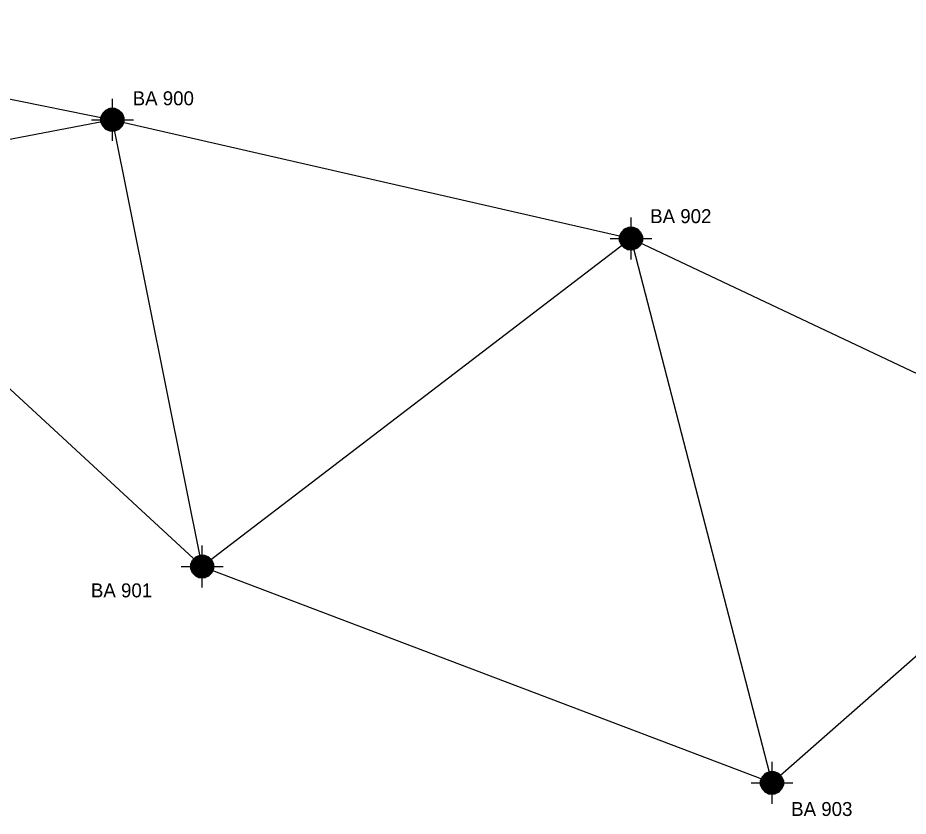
# Model space of a CAD drawing. Extents: x -346533 to -339969, y -1273090 to -1271585.
# Drawn here: x -345166.4 to -344688.1, y -1272911.2 to -1272482.5 of the extents above; entities that cross this region are included whole.
import ezdxf

# ---------------------------------------------------------------- set-up
doc = ezdxf.new("R2010")
doc.units = 0
for name, color, linetype in [('BP_11', 7, 'Continuous'), ('BP_12', 7, 'Continuous'), ('BP_14', 7, 'Continuous')]:
    doc.layers.add(name, color=color, linetype=linetype)

msp = doc.modelspace()

# ---------------------------------------------------------------- linework, layer by layer
at = {"layer": 'BP_11'}
for points in [[(-345115.54, -1272548.47), (-345115.54, -1272542.12), (-345115.54, -1272535.77), (-345115.54, -1272529.42), (-345115.54, -1272525.97)], [(-345115.54, -1272531.07), (-345114.34, -1272531.07), (-345112.09, -1272532.02), (-345110.39, -1272533.72), (-345109.44, -1272535.97), (-345109.44, -1272538.42), (-345110.39, -1272540.67), (-345112.09, -1272542.37), (-345114.34, -1272543.32), (-345116.79, -1272543.32), (-345119.04, -1272542.37), (-345120.74, -1272540.67), (-345121.69, -1272538.42), (-345121.69, -1272535.97), (-345120.74, -1272533.72), (-345119.04, -1272532.02), (-345116.79, -1272531.07), (-345115.59, -1272531.07), (-345113.79, -1272531.42), (-345117.39, -1272531.42), (-345118.19, -1272531.82), (-345112.99, -1272531.82), (-345112.19, -1272532.22), (-345118.54, -1272532.22), (-345118.99, -1272532.22), (-345119.39, -1272532.62), (-345113.04, -1272532.62), (-345111.79, -1272532.62), (-345111.39, -1272533.02), (-345117.74, -1272533.02), (-345119.79, -1272533.02), (-345120.19, -1272533.42), (-345113.84, -1272533.42), (-345110.99, -1272533.42), (-345110.59, -1272533.82), (-345116.94, -1272533.82), (-345120.59, -1272533.82), (-345120.59, -1272534.22), (-345114.24, -1272534.22), (-345110.59, -1272534.22), (-345110.19, -1272534.62), (-345116.54, -1272534.62), (-345120.99, -1272534.62), (-345120.99, -1272535.02), (-345114.64, -1272535.02), (-345110.19, -1272535.02), (-345109.79, -1272535.42), (-345116.14, -1272535.42), (-345121.39, -1272535.42), (-345121.39, -1272535.82), (-345115.04, -1272535.82), (-345109.79, -1272535.82), (-345109.79, -1272536.22), (-345116.14, -1272536.22), (-345121.39, -1272536.22), (-345121.39, -1272536.62), (-345115.04, -1272536.62), (-345109.79, -1272536.62), (-345109.79, -1272537.02), (-345116.14, -1272537.02), (-345121.39, -1272537.02), (-345121.39, -1272537.42), (-345115.04, -1272537.42), (-345109.79, -1272537.42), (-345109.79, -1272537.82), (-345116.14, -1272537.82), (-345121.39, -1272537.82), (-345121.39, -1272538.22), (-345115.04, -1272538.22), (-345109.79, -1272538.22), (-345109.79, -1272538.62), (-345116.14, -1272538.62), (-345121.39, -1272538.62), (-345121.39, -1272539.02), (-345115.04, -1272539.02), (-345109.79, -1272539.02), (-345110.19, -1272539.42), (-345116.54, -1272539.42), (-345120.99, -1272539.42), (-345120.99, -1272539.82), (-345114.64, -1272539.82), (-345110.19, -1272539.82), (-345110.59, -1272540.22), (-345116.94, -1272540.22), (-345120.59, -1272540.22), (-345120.59, -1272540.62), (-345114.24, -1272540.62), (-345110.59, -1272540.62), (-345110.99, -1272541.02), (-345117.34, -1272541.02), (-345120.19, -1272541.02), (-345119.79, -1272541.42), (-345113.44, -1272541.42), (-345111.39, -1272541.42), (-345111.79, -1272541.82), (-345118.14, -1272541.82), (-345119.39, -1272541.82), (-345118.99, -1272542.22), (-345112.64, -1272542.22), (-345112.19, -1272542.22)], [(-345126.79, -1272537.22), (-345120.44, -1272537.22), (-345114.09, -1272537.22), (-345107.74, -1272537.22), (-345104.29, -1272537.22)], [(-345112.19, -1272542.22), (-345112.99, -1272542.62), (-345118.19, -1272542.62), (-345117.39, -1272543.02), (-345113.79, -1272543.02)], [(-344837, -1272612.27), (-344837, -1272605.92), (-344837, -1272599.57), (-344837, -1272593.22), (-344837, -1272589.77)], [(-344837, -1272594.87), (-344835.8, -1272594.87), (-344833.55, -1272595.82), (-344831.85, -1272597.52), (-344830.9, -1272599.77), (-344830.9, -1272602.22), (-344831.85, -1272604.47), (-344833.55, -1272606.17), (-344835.8, -1272607.12), (-344838.25, -1272607.12), (-344840.5, -1272606.17), (-344842.2, -1272604.47), (-344843.15, -1272602.22), (-344843.15, -1272599.77), (-344842.2, -1272597.52), (-344840.5, -1272595.82), (-344838.25, -1272594.87), (-344837.05, -1272594.87), (-344835.25, -1272595.22), (-344838.85, -1272595.22), (-344839.65, -1272595.62), (-344834.45, -1272595.62), (-344833.65, -1272596.02), (-344840, -1272596.02), (-344840.45, -1272596.02), (-344840.85, -1272596.42), (-344834.5, -1272596.42), (-344833.25, -1272596.42), (-344832.85, -1272596.82), (-344839.2, -1272596.82), (-344841.25, -1272596.82), (-344841.65, -1272597.22), (-344835.3, -1272597.22), (-344832.45, -1272597.22), (-344832.05, -1272597.62), (-344838.4, -1272597.62), (-344842.05, -1272597.62), (-344842.05, -1272598.02), (-344835.7, -1272598.02), (-344832.05, -1272598.02), (-344831.65, -1272598.42), (-344838, -1272598.42), (-344842.45, -1272598.42), (-344842.45, -1272598.82), (-344836.1, -1272598.82), (-344831.65, -1272598.82), (-344831.25, -1272599.22), (-344837.6, -1272599.22), (-344842.85, -1272599.22), (-344842.85, -1272599.62), (-344836.5, -1272599.62), (-344831.25, -1272599.62), (-344831.25, -1272600.02), (-344837.6, -1272600.02), (-344842.85, -1272600.02), (-344842.85, -1272600.42), (-344836.5, -1272600.42), (-344831.25, -1272600.42), (-344831.25, -1272600.82), (-344837.6, -1272600.82), (-344842.85, -1272600.82), (-344842.85, -1272601.22), (-344836.5, -1272601.22), (-344831.25, -1272601.22), (-344831.25, -1272601.62), (-344837.6, -1272601.62), (-344842.85, -1272601.62), (-344842.85, -1272602.02), (-344836.5, -1272602.02), (-344831.25, -1272602.02), (-344831.25, -1272602.42), (-344837.6, -1272602.42), (-344842.85, -1272602.42), (-344842.85, -1272602.82), (-344836.5, -1272602.82), (-344831.25, -1272602.82), (-344831.65, -1272603.22), (-344838, -1272603.22), (-344842.45, -1272603.22), (-344842.45, -1272603.62), (-344836.1, -1272603.62), (-344831.65, -1272603.62), (-344832.05, -1272604.02), (-344838.4, -1272604.02), (-344842.05, -1272604.02), (-344842.05, -1272604.42), (-344835.7, -1272604.42), (-344832.05, -1272604.42), (-344832.45, -1272604.82), (-344838.8, -1272604.82), (-344841.65, -1272604.82), (-344841.25, -1272605.22), (-344834.9, -1272605.22), (-344832.85, -1272605.22), (-344833.25, -1272605.62), (-344839.6, -1272605.62), (-344840.85, -1272605.62), (-344840.45, -1272606.02), (-344834.1, -1272606.02), (-344833.65, -1272606.02)], [(-344848.25, -1272601.02), (-344841.9, -1272601.02), (-344835.55, -1272601.02), (-344829.2, -1272601.02), (-344825.75, -1272601.02)], [(-344833.65, -1272606.02), (-344834.45, -1272606.42), (-344839.65, -1272606.42), (-344838.85, -1272606.82), (-344835.25, -1272606.82)], [(-345067.32, -1272788.36), (-345067.32, -1272782.01), (-345067.32, -1272775.66), (-345067.32, -1272769.31), (-345067.32, -1272765.86)], [(-345067.32, -1272770.96), (-345066.12, -1272770.96), (-345063.87, -1272771.91), (-345062.17, -1272773.61), (-345061.22, -1272775.86), (-345061.22, -1272778.31), (-345062.17, -1272780.56), (-345063.87, -1272782.26), (-345066.12, -1272783.21), (-345068.57, -1272783.21), (-345070.82, -1272782.26), (-345072.52, -1272780.56), (-345073.47, -1272778.31), (-345073.47, -1272775.86), (-345072.52, -1272773.61), (-345070.82, -1272771.91), (-345068.57, -1272770.96), (-345067.37, -1272770.96), (-345065.57, -1272771.31), (-345069.17, -1272771.31), (-345069.97, -1272771.71), (-345064.77, -1272771.71), (-345063.97, -1272772.11), (-345070.32, -1272772.11), (-345070.77, -1272772.11), (-345071.17, -1272772.51), (-345064.82, -1272772.51), (-345063.57, -1272772.51), (-345063.17, -1272772.91), (-345069.52, -1272772.91), (-345071.57, -1272772.91), (-345071.97, -1272773.31), (-345065.62, -1272773.31), (-345062.77, -1272773.31), (-345062.37, -1272773.71), (-345068.72, -1272773.71), (-345072.37, -1272773.71), (-345072.37, -1272774.11), (-345066.02, -1272774.11), (-345062.37, -1272774.11), (-345061.97, -1272774.51), (-345068.32, -1272774.51), (-345072.77, -1272774.51), (-345072.77, -1272774.91), (-345066.42, -1272774.91), (-345061.97, -1272774.91), (-345061.57, -1272775.31), (-345067.92, -1272775.31), (-345073.17, -1272775.31), (-345073.17, -1272775.71), (-345066.82, -1272775.71), (-345061.57, -1272775.71), (-345061.57, -1272776.11), (-345067.92, -1272776.11), (-345073.17, -1272776.11), (-345073.17, -1272776.51), (-345066.82, -1272776.51), (-345061.57, -1272776.51), (-345061.57, -1272776.91), (-345067.92, -1272776.91), (-345073.17, -1272776.91), (-345073.17, -1272777.31), (-345066.82, -1272777.31), (-345061.57, -1272777.31), (-345061.57, -1272777.71), (-345067.92, -1272777.71), (-345073.17, -1272777.71), (-345073.17, -1272778.11), (-345066.82, -1272778.11), (-345061.57, -1272778.11), (-345061.57, -1272778.51), (-345067.92, -1272778.51), (-345073.17, -1272778.51), (-345073.17, -1272778.91), (-345066.82, -1272778.91), (-345061.57, -1272778.91), (-345061.97, -1272779.31), (-345068.32, -1272779.31), (-345072.77, -1272779.31), (-345072.77, -1272779.71), (-345066.42, -1272779.71), (-345061.97, -1272779.71), (-345062.37, -1272780.11), (-345068.72, -1272780.11), (-345072.37, -1272780.11), (-345072.37, -1272780.51), (-345066.02, -1272780.51), (-345062.37, -1272780.51), (-345062.77, -1272780.91), (-345069.12, -1272780.91), (-345071.97, -1272780.91), (-345071.57, -1272781.31), (-345065.22, -1272781.31), (-345063.17, -1272781.31), (-345063.57, -1272781.71), (-345069.92, -1272781.71), (-345071.17, -1272781.71), (-345070.77, -1272782.11), (-345064.42, -1272782.11), (-345063.97, -1272782.11)], [(-345078.57, -1272777.11), (-345072.22, -1272777.11), (-345065.87, -1272777.11), (-345059.52, -1272777.11), (-345056.07, -1272777.11)], [(-345063.97, -1272782.11), (-345064.77, -1272782.51), (-345069.97, -1272782.51), (-345069.17, -1272782.91), (-345065.57, -1272782.91)], [(-344761.26, -1272904.52), (-344761.26, -1272898.17), (-344761.26, -1272891.82), (-344761.26, -1272885.47), (-344761.26, -1272882.02)], [(-344761.26, -1272887.12), (-344760.06, -1272887.12), (-344757.81, -1272888.07), (-344756.11, -1272889.77), (-344755.16, -1272892.02), (-344755.16, -1272894.47), (-344756.11, -1272896.72), (-344757.81, -1272898.42), (-344760.06, -1272899.37), (-344762.51, -1272899.37), (-344764.76, -1272898.42), (-344766.46, -1272896.72), (-344767.41, -1272894.47), (-344767.41, -1272892.02), (-344766.46, -1272889.77), (-344764.76, -1272888.07), (-344762.51, -1272887.12), (-344761.31, -1272887.12), (-344759.51, -1272887.47), (-344763.11, -1272887.47), (-344763.91, -1272887.87), (-344758.71, -1272887.87), (-344757.91, -1272888.27), (-344764.26, -1272888.27), (-344764.71, -1272888.27), (-344765.11, -1272888.67), (-344758.76, -1272888.67), (-344757.51, -1272888.67), (-344757.11, -1272889.07), (-344763.46, -1272889.07), (-344765.51, -1272889.07), (-344765.91, -1272889.47), (-344759.56, -1272889.47), (-344756.71, -1272889.47), (-344756.31, -1272889.87), (-344762.66, -1272889.87), (-344766.31, -1272889.87), (-344766.31, -1272890.27), (-344759.96, -1272890.27), (-344756.31, -1272890.27), (-344755.91, -1272890.67), (-344762.26, -1272890.67), (-344766.71, -1272890.67), (-344766.71, -1272891.07), (-344760.36, -1272891.07), (-344755.91, -1272891.07), (-344755.51, -1272891.47), (-344761.86, -1272891.47), (-344767.11, -1272891.47), (-344767.11, -1272891.87), (-344760.76, -1272891.87), (-344755.51, -1272891.87), (-344755.51, -1272892.27), (-344761.86, -1272892.27), (-344767.11, -1272892.27), (-344767.11, -1272892.67), (-344760.76, -1272892.67), (-344755.51, -1272892.67), (-344755.51, -1272893.07), (-344761.86, -1272893.07), (-344767.11, -1272893.07), (-344767.11, -1272893.47), (-344760.76, -1272893.47), (-344755.51, -1272893.47), (-344755.51, -1272893.87), (-344761.86, -1272893.87), (-344767.11, -1272893.87), (-344767.11, -1272894.27), (-344760.76, -1272894.27), (-344755.51, -1272894.27), (-344755.51, -1272894.67), (-344761.86, -1272894.67), (-344767.11, -1272894.67), (-344767.11, -1272895.07), (-344760.76, -1272895.07), (-344755.51, -1272895.07), (-344755.91, -1272895.47), (-344762.26, -1272895.47), (-344766.71, -1272895.47), (-344766.71, -1272895.87), (-344760.36, -1272895.87), (-344755.91, -1272895.87), (-344756.31, -1272896.27), (-344762.66, -1272896.27), (-344766.31, -1272896.27), (-344766.31, -1272896.67), (-344759.96, -1272896.67), (-344756.31, -1272896.67), (-344756.71, -1272897.07), (-344763.06, -1272897.07), (-344765.91, -1272897.07), (-344765.51, -1272897.47), (-344759.16, -1272897.47), (-344757.11, -1272897.47), (-344757.51, -1272897.87), (-344763.86, -1272897.87), (-344765.11, -1272897.87), (-344764.71, -1272898.27), (-344758.36, -1272898.27), (-344757.91, -1272898.27)], [(-344772.51, -1272893.27), (-344766.16, -1272893.27), (-344759.81, -1272893.27), (-344753.46, -1272893.27), (-344750.01, -1272893.27)], [(-344757.91, -1272898.27), (-344758.71, -1272898.67), (-344763.91, -1272898.67), (-344763.11, -1272899.07), (-344759.51, -1272899.07)]]:
    msp.add_lwpolyline(points, dxfattribs=at)
for points in [[(-345114.34, -1272531.07), (-345112.09, -1272532.02), (-345110.39, -1272533.72), (-345109.44, -1272535.97), (-345109.44, -1272538.42), (-345110.39, -1272540.67), (-345112.09, -1272542.37), (-345114.34, -1272543.32), (-345116.79, -1272543.32), (-345119.04, -1272542.37), (-345120.74, -1272540.67), (-345121.69, -1272538.42), (-345121.69, -1272535.97), (-345120.74, -1272533.72), (-345119.04, -1272532.02), (-345116.79, -1272531.07)], [(-344835.8, -1272594.87), (-344833.55, -1272595.82), (-344831.85, -1272597.52), (-344830.9, -1272599.77), (-344830.9, -1272602.22), (-344831.85, -1272604.47), (-344833.55, -1272606.17), (-344835.8, -1272607.12), (-344838.25, -1272607.12), (-344840.5, -1272606.17), (-344842.2, -1272604.47), (-344843.15, -1272602.22), (-344843.15, -1272599.77), (-344842.2, -1272597.52), (-344840.5, -1272595.82), (-344838.25, -1272594.87)], [(-345066.12, -1272770.96), (-345063.87, -1272771.91), (-345062.17, -1272773.61), (-345061.22, -1272775.86), (-345061.22, -1272778.31), (-345062.17, -1272780.56), (-345063.87, -1272782.26), (-345066.12, -1272783.21), (-345068.57, -1272783.21), (-345070.82, -1272782.26), (-345072.52, -1272780.56), (-345073.47, -1272778.31), (-345073.47, -1272775.86), (-345072.52, -1272773.61), (-345070.82, -1272771.91), (-345068.57, -1272770.96)], [(-344760.06, -1272887.12), (-344757.81, -1272888.07), (-344756.11, -1272889.77), (-344755.16, -1272892.02), (-344755.16, -1272894.47), (-344756.11, -1272896.72), (-344757.81, -1272898.42), (-344760.06, -1272899.37), (-344762.51, -1272899.37), (-344764.76, -1272898.42), (-344766.46, -1272896.72), (-344767.41, -1272894.47), (-344767.41, -1272892.02), (-344766.46, -1272889.77), (-344764.76, -1272888.07), (-344762.51, -1272887.12)]]:
    msp.add_lwpolyline(points, close=True, dxfattribs=at)
at = {"layer": 'BP_14'}
for p, q in [((-345386.94, -1272482.47), (-345115.54, -1272537.22)), ((-345386.94, -1272482.47), (-345067.32, -1272777.11)), ((-345115.54, -1272537.22), (-345551.44, -1272620.96)), ((-345115.54, -1272537.22), (-344837, -1272601.02)), ((-345067.32, -1272777.11), (-345115.54, -1272537.22)), ((-344837, -1272601.02), (-345067.32, -1272777.11)), ((-344837, -1272601.02), (-344571.36, -1272726.42)), ((-344761.26, -1272893.27), (-344837, -1272601.02)), ((-344571.36, -1272726.42), (-344761.26, -1272893.27)), ((-345067.32, -1272777.11), (-344761.26, -1272893.27))]:
    msp.add_line(p, q, dxfattribs=at)

# ---------------------------------------------------------------- texts
at = {"layer": 'BP_12'}
for s, p in [('BA 900', (-345104.67, -1272529.43)), ('BA 902', (-344826.72, -1272592.72)), ('BA 901', (-345127.1, -1272793.65)), ('BA 903', (-344750.99, -1272911.05))]:
    msp.add_text(s, height=7.5, dxfattribs=at).set_placement(p)

doc.saveas('drawing.dxf')
